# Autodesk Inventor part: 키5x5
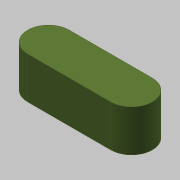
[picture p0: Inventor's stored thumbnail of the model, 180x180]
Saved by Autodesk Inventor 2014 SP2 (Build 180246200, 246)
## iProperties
Created: 2011-04
Part Number: 키5x5
Document SubType Name: Modeling
Designer: pww
Density: 7.86 g/cm^3
Material: 강철, 연강
Appearance: 올리브 녹색
Author: pww
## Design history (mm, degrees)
sketch "스케치1"
  geometry: L1 (-5, -2.5)-(5, -2.5); L2 (5, 2.5)-(-5, 2.5); A1 r 2.5 centre (-5, 0) between (-5, 2.5) and (-5, -2.5); A2 r 2.5 centre (5, 0) between (5, -2.5) and (5, 2.5); 1 further point
  constraints: 4 end point, 4 point on circle, 2 centre point
extrude "돌출1" new body sketch "스케치1" distance "d0" = 5; taper "d1" = 0 deg
node "솔리드1"
